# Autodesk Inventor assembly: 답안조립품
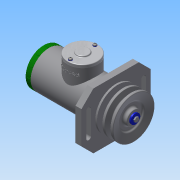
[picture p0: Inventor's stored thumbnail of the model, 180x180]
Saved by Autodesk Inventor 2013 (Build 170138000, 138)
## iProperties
Created: 2017-10
Part Number: 답안조립품
Document SubType Name: Assembly
Designer: Administrator
Author: Administrator
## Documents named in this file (20)
- C:\Users\Administrator\Desktop\471008V1018\답안조립품.iam
- C:\Users\Administrator\Desktop\471008V1018\V-벨트풀리.ipt
- C:\Users\Administrator\Desktop\471008V1018\너트 M10.ipt
- C:\Users\Administrator\Desktop\471008V1018\멈춤링 15 x 1.ipt
- C:\Users\Administrator\Desktop\471008V1018\멈춤링 35x1.6.ipt
- C:\Users\Administrator\Desktop\471008V1018\베어링 15 x 35 x 11.ipt
- C:\Users\Administrator\Desktop\471008V1018\본체.ipt
- C:\Users\Administrator\Desktop\471008V1018\볼트 M4 x 10.ipt
- C:\Users\Administrator\Desktop\471008V1018\부시1.ipt
- C:\Users\Administrator\Desktop\471008V1018\부시2.ipt
- C:\Users\Administrator\Desktop\471008V1018\사이드 커버.ipt
- 사이드 커버.ipt
- C:\Users\Administrator\Desktop\471008V1018\십자볼트 M3 x 10.ipt
- C:\Users\Administrator\Desktop\471008V1018\오일 실 15 25 7.ipt
- C:\Users\Administrator\Desktop\471008V1018\와셔 3x6.ipt
- C:\Users\Administrator\Desktop\471008V1018\와셔 4x16.ipt
- C:\Users\Administrator\Desktop\471008V1018\와셔 10x21.ipt
- C:\Users\Administrator\Desktop\471008V1018\축.ipt
- C:\Users\Administrator\Desktop\471008V1018\키 4 x 4 x 18.ipt
- C:\Users\Administrator\Desktop\471008V1018\탑 커버.ipt
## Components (2 placed, 2 different names)
1. V-벨트풀리:1 — 각도:3
2. ISO 4017 M4 x 10:1
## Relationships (1: Angle 1)
- 각도:3 [Angle]: V-벨트풀리:1
